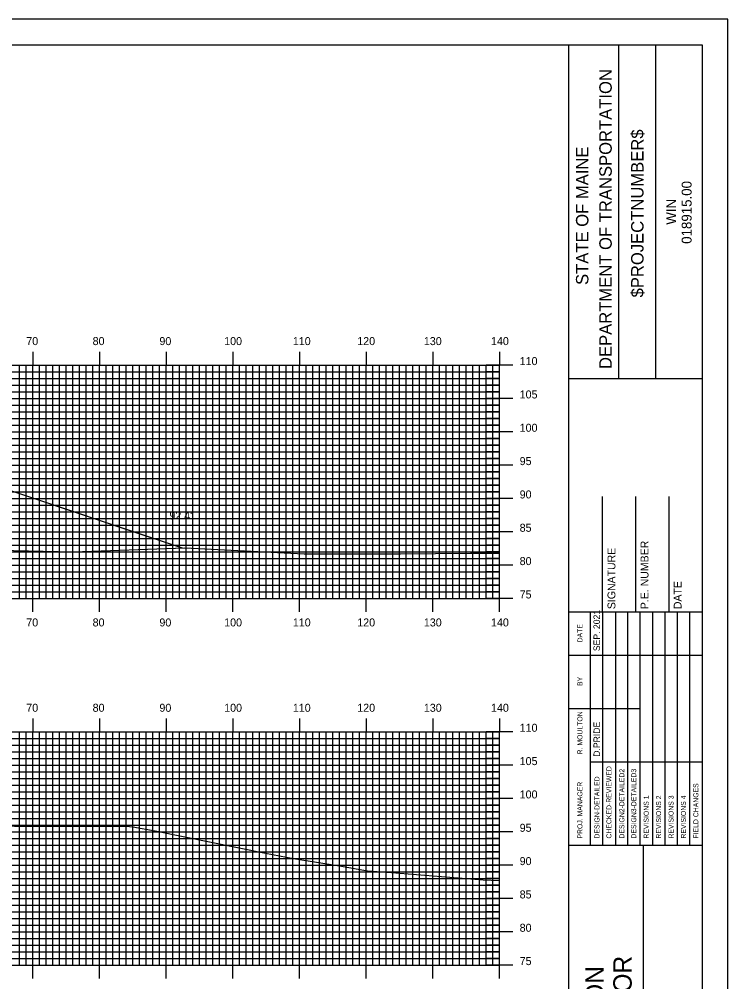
# Model space of a CAD drawing. Extents: x 1755888 to 1756232, y 442591 to 442811.
# Drawn here: x 1756122 to 1756228.3, y 442666.2 to 442810.5 of the extents above; entities that cross this region are included whole.
import ezdxf

# ---------------------------------------------------------------- set-up
doc = ezdxf.new("R2010")
doc.units = 0
for name, color, linetype in [('BORDER', 7, 'Continuous'), ('D_Roadway_Centerline', 7, 'Continuous'), ('D_Roadway_SlopeLines', 7, 'Continuous'), ('D_Text_Standard', 7, 'Continuous'), ('H_V ANNOTATION', 7, 'Continuous'), ('MAJOR', 7, 'Continuous'), ('MINOR', 7, 'Continuous'), ('PLOT BOUNDARY', 7, 'Continuous'), ('S_Roadway_Centerline', 7, 'Continuous')]:
    doc.layers.add(name, color=color, linetype=linetype)

msp = doc.modelspace()

# ---------------------------------------------------------------- linework, layer by layer
at = {"layer": 'BORDER'}
for p, q in [((1756204.46, 442596.67), (1756204.46, 442806.67)), ((1756211.91, 442756.66), (1756211.91, 442806.66)), ((1756217.5, 442756.66), (1756217.5, 442806.66)), ((1756204.46, 442756.65), (1756224.46, 442756.65)), ((1756209.46, 442721.67), (1756209.46, 442738.97)), ((1756214.46, 442721.67), (1756214.46, 442738.97)), ((1756219.46, 442721.67), (1756219.46, 442738.97)), ((1756204.46, 442721.67), (1756224.46, 442721.67)), ((1756204.46, 442686.67), (1756224.46, 442686.67)), ((1756215.64, 442616.67), (1756215.64, 442686.67))]:
    msp.add_line(p, q, dxfattribs=at)
msp.add_lwpolyline([(1755904.46, 442596.67), (1756224.46, 442596.67), (1756224.46, 442806.67), (1755904.46, 442806.67)], close=True, dxfattribs=at)
for points in [[(1756207.69, 442715.17), (1756207.69, 442721.67)], [(1756209.55, 442686.68), (1756209.55, 442721.67)], [(1756211.42, 442721.67), (1756211.42, 442686.68)], [(1756213.28, 442686.68), (1756213.28, 442721.67)], [(1756215.14, 442686.68), (1756215.14, 442721.67)], [(1756217.01, 442686.68), (1756217.01, 442721.67)], [(1756218.87, 442686.68), (1756218.87, 442721.67)], [(1756220.73, 442686.68), (1756220.73, 442721.67)], [(1756222.6, 442686.68), (1756222.6, 442721.67)], [(1756207.69, 442686.68), (1756207.69, 442720.26)], [(1756204.46, 442715.17), (1756224.46, 442715.17)], [(1756204.46, 442707.17), (1756207.69, 442707.17)], [(1756207.69, 442707.17), (1756215.14, 442707.17)], [(1756207.69, 442699.17), (1756224.46, 442699.17)]]:
    msp.add_lwpolyline(points, dxfattribs=at)
at = {"layer": 'D_Roadway_Centerline'}
msp.add_lwpolyline([(1755989.06, 442729.85), (1756026.31, 442748.47), (1756031.06, 442750.85), (1756034.06, 442750.97), (1756042.06, 442751.29), (1756054.06, 442751.53), (1756066.06, 442751.29), (1756066.24, 442751.28), (1756076.73, 442750.8), (1756078.79, 442750.7), (1756080.93, 442750.6), (1756086.8, 442750.32), (1756088.3, 442750.25), (1756089.8, 442750.18), (1756096.45, 442747.96), (1756098.5, 442747.28), (1756103.73, 442745.53), (1756120.4, 442739.96), (1756133.71, 442735.51), (1756138.61, 442733.87), (1756146.45, 442731.25)], dxfattribs=at)
at = {"layer": 'D_Roadway_SlopeLines'}
msp.add_lwpolyline([(1756089.8, 442750.18), (1756146.45, 442731.25)], dxfattribs=at)
at = {"layer": 'MAJOR'}
for p, q in [((1756124.06, 442760.67), (1756124.06, 442758.67)), ((1756134.06, 442760.67), (1756134.06, 442758.67)), ((1756144.06, 442760.67), (1756144.06, 442758.67)), ((1756154.06, 442760.67), (1756154.06, 442758.67)), ((1756164.06, 442760.67), (1756164.06, 442758.67)), ((1756174.06, 442760.67), (1756174.06, 442758.67)), ((1756184.06, 442760.67), (1756184.06, 442758.67)), ((1756194.06, 442760.67), (1756194.06, 442758.67)), ((1755914.06, 442758.67), (1756194.06, 442758.67)), ((1755914.06, 442758.67), (1756194.06, 442758.67)), ((1756124.06, 442723.67), (1756124.06, 442758.67)), ((1756134.06, 442723.67), (1756134.06, 442758.67)), ((1756144.06, 442723.67), (1756144.06, 442758.67)), ((1756154.06, 442723.67), (1756154.06, 442758.67)), ((1756164.06, 442723.67), (1756164.06, 442758.67)), ((1756174.06, 442723.67), (1756174.06, 442758.67)), ((1756184.06, 442723.67), (1756184.06, 442758.67)), ((1756196.06, 442758.67), (1756192.05, 442758.67)), ((1756194.06, 442723.67), (1756194.06, 442758.67)), ((1756194.06, 442723.67), (1756194.06, 442758.67)), ((1755914.06, 442753.67), (1756194.06, 442753.67)), ((1756196.06, 442753.67), (1756192.05, 442753.67)), ((1755914.06, 442748.67), (1756194.06, 442748.67)), ((1756196.06, 442748.67), (1756192.05, 442748.67)), ((1755914.06, 442743.67), (1756194.06, 442743.67)), ((1756196.06, 442743.67), (1756192.05, 442743.67)), ((1755914.06, 442738.67), (1756194.06, 442738.67)), ((1756196.06, 442738.67), (1756192.05, 442738.67)), ((1755914.06, 442733.67), (1756194.06, 442733.67)), ((1756196.06, 442733.67), (1756192.05, 442733.67)), ((1755914.06, 442728.67), (1756194.06, 442728.67)), ((1756196.06, 442728.67), (1756192.05, 442728.67)), ((1755914.06, 442723.67), (1756194.06, 442723.67)), ((1755914.06, 442723.67), (1756194.06, 442723.67)), ((1756124.06, 442721.66), (1756124.06, 442723.67)), ((1756134.06, 442721.66), (1756134.06, 442723.67)), ((1756144.06, 442721.66), (1756144.06, 442723.67)), ((1756154.06, 442721.66), (1756154.06, 442723.67)), ((1756164.06, 442721.66), (1756164.06, 442723.67)), ((1756174.06, 442721.66), (1756174.06, 442723.67)), ((1756184.06, 442721.66), (1756184.06, 442723.67)), ((1756196.06, 442723.67), (1756192.05, 442723.67)), ((1756194.06, 442721.66), (1756194.06, 442723.67)), ((1756124.06, 442705.67), (1756124.06, 442703.67)), ((1756134.06, 442705.67), (1756134.06, 442703.67)), ((1756144.06, 442705.67), (1756144.06, 442703.67)), ((1756154.06, 442705.67), (1756154.06, 442703.67)), ((1756164.06, 442705.67), (1756164.06, 442703.67)), ((1756174.06, 442705.67), (1756174.06, 442703.67)), ((1756184.06, 442705.67), (1756184.06, 442703.67)), ((1756194.06, 442705.67), (1756194.06, 442703.67)), ((1755914.06, 442703.67), (1756194.06, 442703.67)), ((1755914.06, 442703.67), (1756194.06, 442703.67)), ((1756124.06, 442668.67), (1756124.06, 442703.67)), ((1756134.06, 442668.67), (1756134.06, 442703.67)), ((1756144.06, 442668.67), (1756144.06, 442703.67)), ((1756154.06, 442668.67), (1756154.06, 442703.67)), ((1756164.06, 442668.67), (1756164.06, 442703.67)), ((1756174.06, 442668.67), (1756174.06, 442703.67)), ((1756184.06, 442668.67), (1756184.06, 442703.67)), ((1756196.06, 442703.67), (1756192.05, 442703.67)), ((1756194.06, 442668.67), (1756194.06, 442703.67)), ((1756194.06, 442668.67), (1756194.06, 442703.67)), ((1755914.06, 442698.67), (1756194.06, 442698.67)), ((1756196.06, 442698.67), (1756192.05, 442698.67)), ((1755914.06, 442693.67), (1756194.06, 442693.67)), ((1756196.06, 442693.67), (1756192.05, 442693.67)), ((1755914.06, 442688.67), (1756194.06, 442688.67)), ((1756196.06, 442688.67), (1756192.05, 442688.67)), ((1755914.06, 442683.67), (1756194.06, 442683.67)), ((1756196.06, 442683.67), (1756192.05, 442683.67)), ((1755914.06, 442678.67), (1756194.06, 442678.67)), ((1756196.06, 442678.67), (1756192.05, 442678.67)), ((1755914.06, 442673.67), (1756194.06, 442673.67)), ((1756196.06, 442673.67), (1756192.05, 442673.67)), ((1755914.06, 442668.67), (1756194.06, 442668.67)), ((1755914.06, 442668.67), (1756194.06, 442668.67)), ((1756124.06, 442666.66), (1756124.06, 442668.67)), ((1756134.06, 442666.66), (1756134.06, 442668.67)), ((1756144.06, 442666.66), (1756144.06, 442668.67)), ((1756154.06, 442666.66), (1756154.06, 442668.67)), ((1756164.06, 442666.66), (1756164.06, 442668.67)), ((1756174.06, 442666.66), (1756174.06, 442668.67)), ((1756184.06, 442666.66), (1756184.06, 442668.67)), ((1756196.06, 442668.67), (1756192.05, 442668.67)), ((1756194.06, 442666.66), (1756194.06, 442668.67))]:
    msp.add_line(p, q, dxfattribs=at)
at = {"layer": 'MINOR'}
for p, q in [((1756122.06, 442723.67), (1756122.06, 442758.67)), ((1756123.06, 442723.67), (1756123.06, 442758.67)), ((1756125.06, 442723.67), (1756125.06, 442758.67)), ((1756126.06, 442723.67), (1756126.06, 442758.67)), ((1756127.06, 442723.67), (1756127.06, 442758.67)), ((1756128.06, 442723.67), (1756128.06, 442758.67)), ((1756129.06, 442723.67), (1756129.06, 442758.67)), ((1756130.06, 442723.67), (1756130.06, 442758.67)), ((1756131.06, 442723.67), (1756131.06, 442758.67)), ((1756132.06, 442723.67), (1756132.06, 442758.67)), ((1756133.06, 442723.67), (1756133.06, 442758.67)), ((1756135.06, 442723.67), (1756135.06, 442758.67)), ((1756136.06, 442723.67), (1756136.06, 442758.67)), ((1756137.06, 442723.67), (1756137.06, 442758.67)), ((1756138.06, 442723.67), (1756138.06, 442758.67)), ((1756139.06, 442723.67), (1756139.06, 442758.67)), ((1756140.06, 442723.67), (1756140.06, 442758.67)), ((1756141.06, 442723.67), (1756141.06, 442758.67)), ((1756142.06, 442723.67), (1756142.06, 442758.67)), ((1756143.06, 442723.67), (1756143.06, 442758.67)), ((1756145.06, 442723.67), (1756145.06, 442758.67)), ((1756146.06, 442723.67), (1756146.06, 442758.67)), ((1756147.06, 442723.67), (1756147.06, 442758.67)), ((1756148.06, 442723.67), (1756148.06, 442758.67)), ((1756149.06, 442723.67), (1756149.06, 442758.67)), ((1756150.06, 442723.67), (1756150.06, 442758.67)), ((1756151.06, 442723.67), (1756151.06, 442758.67)), ((1756152.06, 442723.67), (1756152.06, 442758.67)), ((1756153.06, 442723.67), (1756153.06, 442758.67)), ((1756155.06, 442723.67), (1756155.06, 442758.67)), ((1756156.06, 442723.67), (1756156.06, 442758.67)), ((1756157.06, 442723.67), (1756157.06, 442758.67)), ((1756158.06, 442723.67), (1756158.06, 442758.67)), ((1756159.06, 442723.67), (1756159.06, 442758.67)), ((1756160.06, 442723.67), (1756160.06, 442758.67)), ((1756161.06, 442723.67), (1756161.06, 442758.67)), ((1756162.06, 442723.67), (1756162.06, 442758.67)), ((1756163.06, 442723.67), (1756163.06, 442758.67)), ((1756165.06, 442723.67), (1756165.06, 442758.67)), ((1756166.06, 442723.67), (1756166.06, 442758.67)), ((1756167.06, 442723.67), (1756167.06, 442758.67)), ((1756168.06, 442723.67), (1756168.06, 442758.67)), ((1756169.06, 442723.67), (1756169.06, 442758.67)), ((1756170.06, 442723.67), (1756170.06, 442758.67)), ((1756171.06, 442723.67), (1756171.06, 442758.67)), ((1756172.06, 442723.67), (1756172.06, 442758.67)), ((1756173.06, 442723.67), (1756173.06, 442758.67)), ((1756175.06, 442723.67), (1756175.06, 442758.67)), ((1756176.06, 442723.67), (1756176.06, 442758.67)), ((1756177.06, 442723.67), (1756177.06, 442758.67)), ((1756178.06, 442723.67), (1756178.06, 442758.67)), ((1756179.06, 442723.67), (1756179.06, 442758.67)), ((1756180.06, 442723.67), (1756180.06, 442758.67)), ((1756181.06, 442723.67), (1756181.06, 442758.67)), ((1756182.06, 442723.67), (1756182.06, 442758.67)), ((1756183.06, 442723.67), (1756183.06, 442758.67)), ((1756185.06, 442723.67), (1756185.06, 442758.67)), ((1756186.06, 442723.67), (1756186.06, 442758.67)), ((1756187.06, 442723.67), (1756187.06, 442758.67)), ((1756188.06, 442723.67), (1756188.06, 442758.67)), ((1756189.06, 442723.67), (1756189.06, 442758.67)), ((1756190.06, 442723.67), (1756190.06, 442758.67)), ((1756191.06, 442723.67), (1756191.06, 442758.67)), ((1756192.06, 442723.67), (1756192.06, 442758.67)), ((1756193.06, 442723.67), (1756193.06, 442758.67)), ((1755914.06, 442757.67), (1756194.06, 442757.67)), ((1756194.06, 442757.67), (1756192.05, 442757.67)), ((1755914.06, 442756.67), (1756194.06, 442756.67)), ((1755914.06, 442755.67), (1756194.06, 442755.67)), ((1756194.06, 442756.67), (1756192.05, 442756.67)), ((1756194.06, 442755.67), (1756192.05, 442755.67)), ((1755914.06, 442754.67), (1756194.06, 442754.67)), ((1756194.06, 442754.67), (1756192.05, 442754.67)), ((1755914.06, 442752.67), (1756194.06, 442752.67)), ((1755914.06, 442751.67), (1756194.06, 442751.67)), ((1756194.06, 442752.67), (1756192.05, 442752.67)), ((1756194.06, 442751.67), (1756192.05, 442751.67)), ((1755914.06, 442750.67), (1756194.06, 442750.67)), ((1756194.06, 442750.67), (1756192.05, 442750.67)), ((1755914.06, 442749.67), (1756194.06, 442749.67)), ((1756194.06, 442749.67), (1756192.05, 442749.67)), ((1755914.06, 442747.67), (1756194.06, 442747.67)), ((1756194.06, 442747.67), (1756192.05, 442747.67)), ((1755914.06, 442746.67), (1756194.06, 442746.67)), ((1755914.06, 442745.67), (1756194.06, 442745.67)), ((1756194.06, 442746.67), (1756192.05, 442746.67)), ((1756194.06, 442745.67), (1756192.05, 442745.67)), ((1755914.06, 442744.67), (1756194.06, 442744.67)), ((1756194.06, 442744.67), (1756192.05, 442744.67)), ((1755914.06, 442742.67), (1756194.06, 442742.67)), ((1756194.06, 442742.67), (1756192.05, 442742.67)), ((1755914.06, 442741.67), (1756194.06, 442741.67)), ((1756194.06, 442741.67), (1756192.05, 442741.67)), ((1755914.06, 442740.67), (1756194.06, 442740.67)), ((1756194.06, 442740.67), (1756192.05, 442740.67)), ((1755914.06, 442739.67), (1756194.06, 442739.67)), ((1756194.06, 442739.67), (1756192.05, 442739.67)), ((1755914.06, 442737.67), (1756194.06, 442737.67)), ((1756194.06, 442737.67), (1756192.05, 442737.67)), ((1755914.06, 442736.67), (1756194.06, 442736.67)), ((1755914.06, 442735.67), (1756194.06, 442735.67)), ((1756194.06, 442736.67), (1756192.05, 442736.67)), ((1756194.06, 442735.67), (1756192.05, 442735.67)), ((1755914.06, 442734.67), (1756194.06, 442734.67)), ((1756194.06, 442734.67), (1756192.05, 442734.67)), ((1755914.06, 442732.67), (1756194.06, 442732.67)), ((1756194.06, 442732.67), (1756192.05, 442732.67)), ((1755914.06, 442731.67), (1756194.06, 442731.67)), ((1756194.06, 442731.67), (1756192.05, 442731.67)), ((1755914.06, 442730.67), (1756194.06, 442730.67)), ((1755914.06, 442729.67), (1756194.06, 442729.67)), ((1756194.06, 442730.67), (1756192.05, 442730.67)), ((1756194.06, 442729.67), (1756192.05, 442729.67)), ((1755914.06, 442727.67), (1756194.06, 442727.67)), ((1756194.06, 442727.67), (1756192.05, 442727.67)), ((1755914.06, 442726.67), (1756194.06, 442726.67)), ((1755914.06, 442725.67), (1756194.06, 442725.67)), ((1756194.06, 442726.67), (1756192.05, 442726.67)), ((1756194.06, 442725.67), (1756192.05, 442725.67)), ((1755914.06, 442724.67), (1756194.06, 442724.67)), ((1756194.06, 442724.67), (1756192.05, 442724.67)), ((1756122.06, 442668.67), (1756122.06, 442703.67)), ((1756123.06, 442668.67), (1756123.06, 442703.67)), ((1756125.06, 442668.67), (1756125.06, 442703.67)), ((1756126.06, 442668.67), (1756126.06, 442703.67)), ((1756127.06, 442668.67), (1756127.06, 442703.67)), ((1756128.06, 442668.67), (1756128.06, 442703.67)), ((1756129.06, 442668.67), (1756129.06, 442703.67)), ((1756130.06, 442668.67), (1756130.06, 442703.67)), ((1756131.06, 442668.67), (1756131.06, 442703.67)), ((1756132.06, 442668.67), (1756132.06, 442703.67)), ((1756133.06, 442668.67), (1756133.06, 442703.67)), ((1756135.06, 442668.67), (1756135.06, 442703.67)), ((1756136.06, 442668.67), (1756136.06, 442703.67)), ((1756137.06, 442668.67), (1756137.06, 442703.67)), ((1756138.06, 442668.67), (1756138.06, 442703.67)), ((1756139.06, 442668.67), (1756139.06, 442703.67)), ((1756140.06, 442668.67), (1756140.06, 442703.67)), ((1756141.06, 442668.67), (1756141.06, 442703.67)), ((1756142.06, 442668.67), (1756142.06, 442703.67)), ((1756143.06, 442668.67), (1756143.06, 442703.67)), ((1756145.06, 442668.67), (1756145.06, 442703.67)), ((1756146.06, 442668.67), (1756146.06, 442703.67)), ((1756147.06, 442668.67), (1756147.06, 442703.67)), ((1756148.06, 442668.67), (1756148.06, 442703.67)), ((1756149.06, 442668.67), (1756149.06, 442703.67)), ((1756150.06, 442668.67), (1756150.06, 442703.67)), ((1756151.06, 442668.67), (1756151.06, 442703.67)), ((1756152.06, 442668.67), (1756152.06, 442703.67)), ((1756153.06, 442668.67), (1756153.06, 442703.67)), ((1756155.06, 442668.67), (1756155.06, 442703.67)), ((1756156.06, 442668.67), (1756156.06, 442703.67)), ((1756157.06, 442668.67), (1756157.06, 442703.67)), ((1756158.06, 442668.67), (1756158.06, 442703.67)), ((1756159.06, 442668.67), (1756159.06, 442703.67)), ((1756160.06, 442668.67), (1756160.06, 442703.67)), ((1756161.06, 442668.67), (1756161.06, 442703.67)), ((1756162.06, 442668.67), (1756162.06, 442703.67)), ((1756163.06, 442668.67), (1756163.06, 442703.67)), ((1756165.06, 442668.67), (1756165.06, 442703.67)), ((1756166.06, 442668.67), (1756166.06, 442703.67)), ((1756167.06, 442668.67), (1756167.06, 442703.67)), ((1756168.06, 442668.67), (1756168.06, 442703.67)), ((1756169.06, 442668.67), (1756169.06, 442703.67)), ((1756170.06, 442668.67), (1756170.06, 442703.67)), ((1756171.06, 442668.67), (1756171.06, 442703.67)), ((1756172.06, 442668.67), (1756172.06, 442703.67)), ((1756173.06, 442668.67), (1756173.06, 442703.67)), ((1756175.06, 442668.67), (1756175.06, 442703.67)), ((1756176.06, 442668.67), (1756176.06, 442703.67)), ((1756177.06, 442668.67), (1756177.06, 442703.67)), ((1756178.06, 442668.67), (1756178.06, 442703.67)), ((1756179.06, 442668.67), (1756179.06, 442703.67)), ((1756180.06, 442668.67), (1756180.06, 442703.67)), ((1756181.06, 442668.67), (1756181.06, 442703.67)), ((1756182.06, 442668.67), (1756182.06, 442703.67)), ((1756183.06, 442668.67), (1756183.06, 442703.67)), ((1756185.06, 442668.67), (1756185.06, 442703.67)), ((1756186.06, 442668.67), (1756186.06, 442703.67)), ((1756187.06, 442668.67), (1756187.06, 442703.67)), ((1756188.06, 442668.67), (1756188.06, 442703.67)), ((1756189.06, 442668.67), (1756189.06, 442703.67)), ((1756190.06, 442668.67), (1756190.06, 442703.67)), ((1756191.06, 442668.67), (1756191.06, 442703.67)), ((1756192.06, 442668.67), (1756192.06, 442703.67)), ((1756193.06, 442668.67), (1756193.06, 442703.67)), ((1755914.06, 442702.67), (1756194.06, 442702.67)), ((1756194.06, 442702.67), (1756192.05, 442702.67)), ((1755914.06, 442701.67), (1756194.06, 442701.67)), ((1756194.06, 442701.67), (1756192.05, 442701.67)), ((1755914.06, 442700.67), (1756194.06, 442700.67)), ((1755914.06, 442699.67), (1756194.06, 442699.67)), ((1756194.06, 442700.67), (1756192.05, 442700.67)), ((1756194.06, 442699.67), (1756192.05, 442699.67)), ((1755914.06, 442697.67), (1756194.06, 442697.67)), ((1755914.06, 442696.67), (1756194.06, 442696.67)), ((1756194.06, 442697.67), (1756192.05, 442697.67)), ((1756194.06, 442696.67), (1756192.05, 442696.67)), ((1755914.06, 442695.67), (1756194.06, 442695.67)), ((1756194.06, 442695.67), (1756192.05, 442695.67)), ((1755914.06, 442694.67), (1756194.06, 442694.67)), ((1756194.06, 442694.67), (1756192.05, 442694.67)), ((1755914.06, 442692.67), (1756194.06, 442692.67)), ((1756194.06, 442692.67), (1756192.05, 442692.67)), ((1755914.06, 442691.67), (1756194.06, 442691.67)), ((1755914.06, 442690.67), (1756194.06, 442690.67)), ((1756194.06, 442691.67), (1756192.05, 442691.67)), ((1756194.06, 442690.67), (1756192.05, 442690.67)), ((1755914.06, 442689.67), (1756194.06, 442689.67)), ((1756194.06, 442689.67), (1756192.05, 442689.67)), ((1755914.06, 442687.67), (1756194.06, 442687.67)), ((1755914.06, 442686.67), (1756194.06, 442686.67)), ((1756194.06, 442687.67), (1756192.05, 442687.67)), ((1756194.06, 442686.67), (1756192.05, 442686.67)), ((1755914.06, 442685.67), (1756194.06, 442685.67)), ((1756194.06, 442685.67), (1756192.05, 442685.67)), ((1755914.06, 442684.67), (1756194.06, 442684.67)), ((1756194.06, 442684.67), (1756192.05, 442684.67)), ((1755914.06, 442682.67), (1756194.06, 442682.67)), ((1756194.06, 442682.67), (1756192.05, 442682.67)), ((1755914.06, 442681.67), (1756194.06, 442681.67)), ((1755914.06, 442680.67), (1756194.06, 442680.67)), ((1756194.06, 442681.67), (1756192.05, 442681.67)), ((1756194.06, 442680.67), (1756192.05, 442680.67)), ((1755914.06, 442679.67), (1756194.06, 442679.67)), ((1756194.06, 442679.67), (1756192.05, 442679.67)), ((1755914.06, 442677.67), (1756194.06, 442677.67)), ((1756194.06, 442677.67), (1756192.05, 442677.67)), ((1755914.06, 442676.67), (1756194.06, 442676.67)), ((1756194.06, 442676.67), (1756192.05, 442676.67)), ((1755914.06, 442675.67), (1756194.06, 442675.67)), ((1756194.06, 442675.67), (1756192.05, 442675.67)), ((1755914.06, 442674.67), (1756194.06, 442674.67)), ((1756194.06, 442674.67), (1756192.05, 442674.67)), ((1755914.06, 442672.67), (1756194.06, 442672.67)), ((1756194.06, 442672.67), (1756192.05, 442672.67)), ((1755914.06, 442671.67), (1756194.06, 442671.67)), ((1755914.06, 442670.67), (1756194.06, 442670.67)), ((1756194.06, 442671.67), (1756192.05, 442671.67)), ((1756194.06, 442670.67), (1756192.05, 442670.67)), ((1755914.06, 442669.67), (1756194.06, 442669.67)), ((1756194.06, 442669.67), (1756192.05, 442669.67))]:
    msp.add_line(p, q, dxfattribs=at)
at = {"layer": 'PLOT BOUNDARY'}
msp.add_lwpolyline([(1755888.27, 442590.55), (1756228.27, 442590.55), (1756228.27, 442810.55), (1755888.27, 442810.55)], close=True, dxfattribs=at)
at = {"layer": 'S_Roadway_Centerline'}
for points in [[(1755914.06, 442729.3), (1755929.02, 442728.93), (1755936.66, 442728.91), (1755939.99, 442729.1), (1755959.43, 442728.85), (1755985.74, 442729.81), (1755998.98, 442729.96), (1756004.62, 442729.97), (1756047.7, 442730.01), (1756053.19, 442730.1), (1756057.32, 442730.2), (1756075.29, 442730.61), (1756080.95, 442730.51), (1756083.99, 442730.88), (1756088.01, 442730.38), (1756098.56, 442731.95), (1756111.81, 442731.35), (1756118.83, 442730.91), (1756130.1, 442730.66), (1756146.83, 442731.27), (1756164.74, 442730.34), (1756179.2, 442730.36), (1756189.71, 442730.46), (1756194.06, 442730.48)], [(1756011.42, 442679.93), (1756013.98, 442680.37), (1756038.59, 442684.16), (1756041.87, 442684.67), (1756042.88, 442684.71), (1756044.46, 442684.8), (1756060.28, 442685.47), (1756075.57, 442688.67), (1756079.71, 442689.2), (1756081.97, 442689.65), (1756090.36, 442690.02), (1756099.67, 442689.94), (1756106.38, 442690.09), (1756121.31, 442689.5), (1756138.05, 442689.49), (1756139.02, 442689.39), (1756142.39, 442688.79), (1756158.92, 442685.48), (1756163.12, 442684.67), (1756170.03, 442683.56), (1756174.25, 442682.82), (1756177.85, 442682.58), (1756191.59, 442681.48), (1756194.06, 442681.35)]]:
    msp.add_lwpolyline(points, dxfattribs=at)

# ---------------------------------------------------------------- texts
at = {"layer": 'BORDER'}
for s, height, p in [('DEPARTMENT OF TRANSPORTATION', 1.8635, (1756210.87, 442758.08)), ('$PROJECTNUMBER$', 1.8635, (1756215.64, 442768.82)), ('STATE OF MAINE', 1.8635, (1756207.37, 442770.69)), ('018915.00', 1.491, (1756222.85, 442776.86)), ('WIN', 1.491, (1756220.53, 442779.73)), ('SIGNATURE', 1.181, (1756211.42, 442722.06)), ('P.E. NUMBER', 1.1811, (1756216.38, 442722.06)), ('DATE', 1.181, (1756221.34, 442722.06)), ('SEP. 2021', 0.969, (1756209.1, 442715.76)), ('DATE', 0.743, (1756206.47, 442717.08)), ('BY', 0.743, (1756206.47, 442710.54)), ('R. MOULTON', 0.745, (1756206.47, 442700.28)), ('D.PRIDE', 0.969, (1756209.1, 442699.92)), ('CHECKED-REVIEWED', 0.7455, (1756210.82, 442687.65)), ('DESIGN-DETAILED', 0.7455, (1756209.03, 442687.65)), ('DESIGN2-DETAILED2', 0.7455, (1756212.76, 442687.65)), ('DESIGN3-DETAILED3', 0.7455, (1756214.55, 442687.65)), ('PROJ. MANAGER', 0.7455, (1756206.47, 442687.65)), ('FIELD CHANGES', 0.7455, (1756223.86, 442687.65)), ('REVISIONS 1', 0.7455, (1756216.41, 442687.65)), ('REVISIONS 2', 0.7455, (1756218.27, 442687.65)), ('REVISIONS 3', 0.7455, (1756220.14, 442687.65)), ('REVISIONS 4', 0.7455, (1756222, 442687.65)), ('1-395/ROUTE 9 CONNECTOR', 2.7557, (1756213.86, 442618.87)), ('BREWER TO EDDINGTON', 2.7557, (1756209.68, 442623.07))]:
    msp.add_text(s, height=height, rotation=90, dxfattribs=at).set_placement(p)
at = {"layer": 'D_Text_Standard'}
msp.add_text("92.4'", height=1.2, dxfattribs=at).set_placement((1756144.52, 442735.51))
at = {"layer": 'H_V ANNOTATION'}
for s, p in [('70', (1756123.06, 442761.67)), ('80', (1756133.01, 442761.67)), ('90', (1756143.03, 442761.67)), ('100', (1756152.74, 442761.67)), ('110', (1756163.04, 442761.67)), ('120', (1756172.7, 442761.67)), ('130', (1756182.69, 442761.67)), ('140', (1756192.76, 442761.67)), ('110', (1756197.06, 442758.67)), ('105', (1756197.06, 442753.67)), ('100', (1756197.06, 442748.67)), ('95', (1756197.06, 442743.67)), ('90', (1756197.06, 442738.67)), ('85', (1756197.06, 442733.67)), ('80', (1756197.06, 442728.67)), ('75', (1756197.06, 442723.67)), ('70', (1756123.06, 442719.47)), ('80', (1756133.01, 442719.47)), ('90', (1756143.03, 442719.47)), ('100', (1756152.74, 442719.47)), ('110', (1756163.04, 442719.47)), ('120', (1756172.7, 442719.47)), ('130', (1756182.69, 442719.47)), ('140', (1756192.76, 442719.47)), ('70', (1756123.06, 442706.67)), ('80', (1756133.01, 442706.67)), ('90', (1756143.03, 442706.67)), ('100', (1756152.74, 442706.67)), ('110', (1756163.04, 442706.67)), ('120', (1756172.7, 442706.67)), ('130', (1756182.69, 442706.67)), ('140', (1756192.76, 442706.67)), ('110', (1756197.06, 442703.67)), ('105', (1756197.06, 442698.67)), ('100', (1756197.06, 442693.67)), ('95', (1756197.06, 442688.67)), ('90', (1756197.06, 442683.67)), ('85', (1756197.06, 442678.67)), ('80', (1756197.06, 442673.67)), ('75', (1756197.06, 442668.67))]:
    msp.add_text(s, height=1.2, dxfattribs=at).set_placement(p)

doc.saveas('drawing.dxf')
